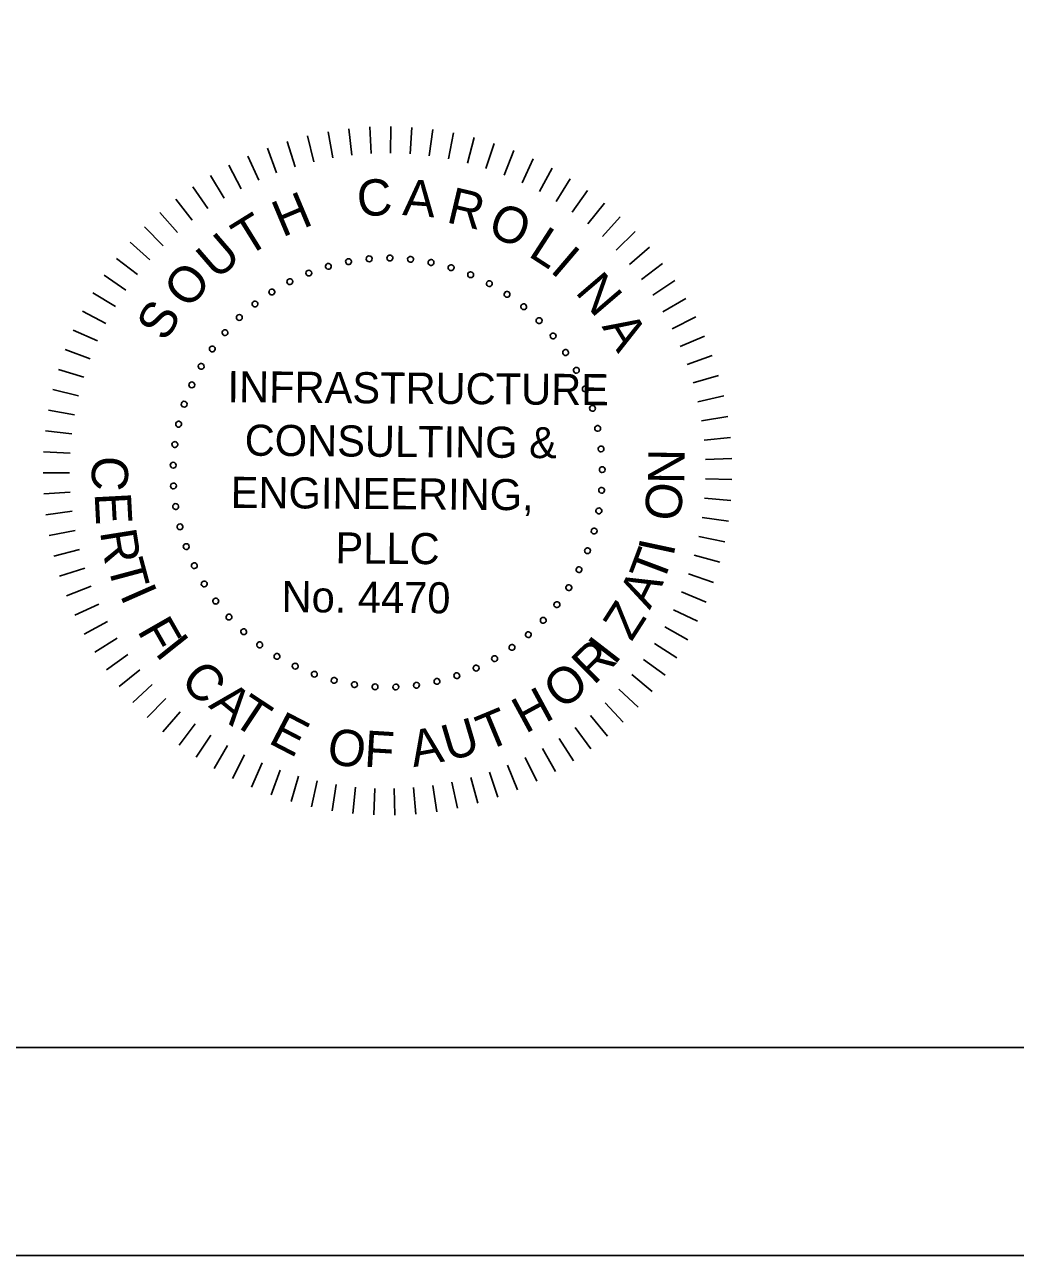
# Model space of a CAD drawing. Extents: x -125.5 to -89.3, y 42.4 to 64.4.
# Drawn here: x -100.072 to -97.692, y 42.449 to 45.407 of the extents above; entities that cross this region are included whole.
import ezdxf

# ---------------------------------------------------------------- set-up
doc = ezdxf.new("R2010")
doc.units = 0
for name, color, linetype in [('BR_BORDER LINES', 7, 'Continuous'), ('BR_TEXT', 7, 'Continuous'), ('Level 31', 7, 'Continuous')]:
    doc.layers.add(name, color=color, linetype=linetype)

msp = doc.modelspace()

# ---------------------------------------------------------------- linework, layer by layer
at = {"layer": 'BR_BORDER LINES'}
msp.add_line((-123.6994, 42.9486), (-90.0334, 42.9486), dxfattribs=at)
at = {"layer": 'BR_TEXT'}
for p, q in [((-99.343, 45.1496), (-99.332, 45.0869)), ((-99.2931, 45.1568), (-99.2858, 45.0935)), ((-99.2427, 45.1609), (-99.2394, 45.0974)), ((-99.1923, 45.162), (-99.1928, 45.0983)), ((-99.1418, 45.16), (-99.1462, 45.0965)), ((-99.0916, 45.1549), (-99.0999, 45.0918)), ((-99.0418, 45.1468), (-99.0539, 45.0842)), ((-99.4412, 45.1262), (-99.4226, 45.0653)), ((-99.3925, 45.1394), (-99.3776, 45.0775)), ((-98.9925, 45.1356), (-99.0084, 45.0739)), ((-98.9441, 45.1214), (-98.9637, 45.0609)), ((-99.5358, 45.0909), (-99.5099, 45.0328)), ((-99.489, 45.11), (-99.4667, 45.0504)), ((-98.8966, 45.1044), (-98.9199, 45.0451)), ((-99.5813, 45.0691), (-99.5519, 45.0126)), ((-98.8502, 45.0844), (-98.877, 45.0267)), ((-98.8051, 45.0617), (-98.8354, 45.0057)), ((-99.6253, 45.0445), (-99.5926, 44.9899)), ((-98.7615, 45.0363), (-98.7952, 44.9822)), ((-99.6678, 45.0172), (-99.6318, 44.9647)), ((-98.7195, 45.0082), (-98.7564, 44.9563)), ((-99.7086, 44.9874), (-99.6694, 44.9372)), ((-98.6793, 44.9777), (-98.7193, 44.9281)), ((-99.7475, 44.9552), (-99.7053, 44.9075)), ((-98.6411, 44.9447), (-98.684, 44.8977)), ((-99.7843, 44.9207), (-99.7393, 44.8756)), ((-98.6049, 44.9095), (-98.6506, 44.8652)), ((-99.819, 44.884), (-99.7713, 44.8418)), ((-98.571, 44.8722), (-98.6193, 44.8307)), ((-99.8513, 44.8452), (-99.8012, 44.806)), ((-98.5393, 44.8328), (-98.5901, 44.7944)), ((-99.8813, 44.8046), (-99.8288, 44.7685)), ((-98.5102, 44.7916), (-98.5632, 44.7564)), ((-99.9087, 44.7622), (-99.8541, 44.7293)), ((-98.4836, 44.7487), (-98.5387, 44.7167)), ((-99.9334, 44.7182), (-99.877, 44.6887)), ((-98.4597, 44.7042), (-98.5166, 44.6757)), ((-99.9555, 44.6728), (-99.8973, 44.6468)), ((-98.4385, 44.6584), (-98.497, 44.6334)), ((-99.9747, 44.6261), (-99.9151, 44.6037)), ((-98.4201, 44.6114), (-98.4801, 44.59)), ((-99.991, 44.5783), (-99.9302, 44.5596)), ((-98.4047, 44.5633), (-98.4659, 44.5456)), ((-100.0044, 44.5297), (-99.9426, 44.5147)), ((-98.3922, 44.5144), (-98.4544, 44.5005)), ((-100.0149, 44.4803), (-99.9522, 44.4691)), ((-98.3828, 44.4648), (-98.4456, 44.4547)), ((-100.0222, 44.4303), (-99.959, 44.423)), ((-98.3763, 44.4147), (-98.4397, 44.4085)), ((-100.0266, 44.38), (-99.963, 44.3766)), ((-98.373, 44.3644), (-98.4366, 44.362)), ((-100.0278, 44.3296), (-99.9641, 44.33)), ((-98.3727, 44.3139), (-98.4363, 44.3154)), ((-100.026, 44.2791), (-99.9625, 44.2834)), ((-98.3755, 44.2635), (-98.4389, 44.2688)), ((-100.0211, 44.2289), (-99.9579, 44.2371)), ((-98.3813, 44.2133), (-98.4443, 44.2226)), ((-100.0131, 44.179), (-99.9506, 44.191)), ((-98.3902, 44.1636), (-98.4525, 44.1767)), ((-100.0021, 44.1297), (-99.9405, 44.1455)), ((-98.4021, 44.1146), (-98.4635, 44.1314)), ((-99.9882, 44.0812), (-99.9276, 44.1008)), ((-98.417, 44.0663), (-98.4773, 44.0869)), ((-99.9713, 44.0336), (-99.912, 44.0569)), ((-98.4348, 44.0191), (-98.4937, 44.0433)), ((-99.9515, 43.9872), (-99.8937, 44.014)), ((-98.4554, 43.973), (-98.5128, 44.0007)), ((-99.9289, 43.942), (-99.8729, 43.9723)), ((-99.9037, 43.8983), (-99.8496, 43.9319)), ((-98.4789, 43.9283), (-98.5344, 43.9595)), ((-98.5049, 43.8851), (-98.5585, 43.9196)), ((-99.8758, 43.8563), (-99.8239, 43.8931)), ((-98.5336, 43.8435), (-98.5849, 43.8812)), ((-99.8454, 43.8159), (-99.7958, 43.8559)), ((-98.5648, 43.8038), (-98.6137, 43.8446)), ((-99.8126, 43.7776), (-99.7655, 43.8205)), ((-99.7775, 43.7413), (-99.7331, 43.7869)), ((-98.5983, 43.7661), (-98.6447, 43.8097)), ((-99.7403, 43.7072), (-99.6988, 43.7555)), ((-98.6341, 43.7304), (-98.6777, 43.7768)), ((-99.701, 43.6754), (-99.6626, 43.7261)), ((-98.6719, 43.697), (-98.7126, 43.746)), ((-99.6599, 43.6461), (-99.6246, 43.6991)), ((-98.7118, 43.666), (-98.7494, 43.7174)), ((-99.6171, 43.6193), (-99.5851, 43.6744)), ((-98.7967, 43.6116), (-98.8278, 43.6671)), ((-98.7534, 43.6375), (-98.7879, 43.6911)), ((-99.5728, 43.5953), (-99.5442, 43.6521)), ((-98.8416, 43.5883), (-98.8692, 43.6457)), ((-99.527, 43.5739), (-99.5019, 43.6324)), ((-99.48, 43.5554), (-99.4586, 43.6153)), ((-98.935, 43.5502), (-98.9555, 43.6105)), ((-98.8877, 43.5679), (-98.9118, 43.6268)), ((-99.432, 43.5398), (-99.4143, 43.6009)), ((-99.3832, 43.5271), (-99.3692, 43.5892)), ((-99.3336, 43.5175), (-99.3234, 43.5803)), ((-99.0821, 43.5151), (-99.0913, 43.5781)), ((-99.0324, 43.5238), (-99.0454, 43.5861)), ((-98.9833, 43.5355), (-99.0001, 43.597)), ((-99.2836, 43.5108), (-99.2772, 43.5742)), ((-99.2332, 43.5073), (-99.2307, 43.5709)), ((-99.1827, 43.5068), (-99.1841, 43.5705)), ((-99.1323, 43.5094), (-99.1376, 43.5729))]:
    msp.add_line(p, q, dxfattribs=at)
for centre, start, end in [((-99.2445, 44.844), 5.0653, 185.0653), ((-99.1947, 44.8459), 359.5268, 179.5268), ((-99.145, 44.8429), 353.9884, 173.9884), ((-99.3424, 44.8258), 16.1422, 196.1422), ((-99.3424, 44.8258), 196.1422, 16.1422), ((-99.2939, 44.8373), 10.6038, 190.6038), ((-99.2939, 44.8373), 190.6038, 10.6038), ((-99.2445, 44.844), 185.0653, 5.0653), ((-99.1947, 44.8459), 179.5268, 359.5268), ((-99.145, 44.8429), 173.9884, 353.9884), ((-99.0957, 44.8352), 168.4499, 348.4499), ((-99.0957, 44.8352), 348.4499, 168.4499), ((-99.0475, 44.8228), 162.9114, 342.9114), ((-99.0475, 44.8228), 342.9114, 162.9114), ((-99.435, 44.7892), 27.2191, 207.2191), ((-99.435, 44.7892), 207.2191, 27.2191), ((-99.3895, 44.8098), 21.6807, 201.6807), ((-99.3895, 44.8098), 201.6807, 21.6807), ((-99.0006, 44.8058), 157.373, 337.373), ((-99.0006, 44.8058), 337.373, 157.373), ((-98.9557, 44.7843), 331.8345, 151.8345), ((-99.4782, 44.7644), 32.7576, 212.7576), ((-99.4782, 44.7644), 212.7576, 32.7576), ((-98.9557, 44.7843), 151.8345, 331.8345), ((-98.913, 44.7586), 146.2961, 326.2961), ((-98.913, 44.7586), 326.2961, 146.2961), ((-99.5188, 44.7355), 38.2961, 218.2961), ((-99.5188, 44.7355), 218.2961, 38.2961), ((-98.873, 44.7289), 140.7576, 320.7576), ((-98.873, 44.7289), 320.7576, 140.7576), ((-99.5564, 44.7029), 43.8345, 223.8345), ((-99.5564, 44.7029), 223.8345, 43.8345), ((-98.836, 44.6955), 315.2191, 135.2191), ((-99.5907, 44.6667), 49.373, 229.373), ((-99.5907, 44.6667), 229.373, 49.373), ((-98.836, 44.6955), 135.2191, 315.2191), ((-98.8024, 44.6587), 129.6807, 309.6807), ((-98.8024, 44.6587), 309.6807, 129.6807), ((-99.6214, 44.6275), 54.9114, 234.9114), ((-99.6214, 44.6275), 234.9114, 54.9114), ((-98.7726, 44.6188), 124.1422, 304.1422), ((-98.7726, 44.6188), 304.1422, 124.1422), ((-99.6481, 44.5854), 60.4499, 240.4499), ((-99.6481, 44.5854), 240.4499, 60.4499), ((-98.7467, 44.5762), 118.6038, 298.6038), ((-98.7467, 44.5762), 298.6038, 118.6038), ((-99.6706, 44.541), 65.9884, 245.9884), ((-99.6706, 44.541), 245.9884, 65.9884), ((-98.7251, 44.5313), 113.0653, 293.0653), ((-98.7251, 44.5313), 293.0653, 113.0653), ((-99.6888, 44.4946), 71.5268, 251.5268), ((-99.6888, 44.4946), 251.5268, 71.5268), ((-98.7079, 44.4845), 107.5268, 287.5268), ((-98.7079, 44.4845), 287.5268, 107.5268), ((-99.7024, 44.4466), 77.0653, 257.0653), ((-99.7024, 44.4466), 257.0653, 77.0653), ((-98.6953, 44.4363), 101.9884, 281.9884), ((-98.6953, 44.4363), 281.9884, 101.9884), ((-99.7113, 44.3976), 82.6038, 262.6038), ((-99.7113, 44.3976), 262.6038, 82.6038), ((-98.6874, 44.3871), 96.4499, 276.4499), ((-98.6874, 44.3871), 276.4499, 96.4499), ((-99.7154, 44.3479), 88.1422, 268.1422), ((-99.7154, 44.3479), 268.1422, 88.1422), ((-98.6843, 44.3374), 90.9114, 270.9114), ((-98.6843, 44.3374), 270.9114, 90.9114), ((-99.7147, 44.2981), 93.6807, 273.6807), ((-99.7147, 44.2981), 273.6807, 93.6807), ((-98.686, 44.2876), 85.373, 265.373), ((-98.686, 44.2876), 265.373, 85.373), ((-99.7092, 44.2486), 99.2191, 279.2191), ((-99.7092, 44.2486), 279.2191, 99.2191), ((-98.6926, 44.2382), 79.8345, 259.8345), ((-98.6926, 44.2382), 259.8345, 79.8345), ((-99.6989, 44.1998), 104.7576, 284.7576), ((-99.6989, 44.1998), 284.7576, 104.7576), ((-98.7038, 44.1896), 74.2961, 254.2961), ((-98.7038, 44.1896), 254.2961, 74.2961), ((-99.684, 44.1523), 110.2961, 290.2961), ((-99.684, 44.1523), 290.2961, 110.2961), ((-98.7197, 44.1424), 68.7576, 248.7576), ((-98.7197, 44.1424), 248.7576, 68.7576), ((-99.6646, 44.1064), 115.8345, 295.8345), ((-99.6646, 44.1064), 295.8345, 115.8345), ((-98.7401, 44.0969), 63.2191, 243.2191), ((-98.7401, 44.0969), 243.2191, 63.2191), ((-99.6408, 44.0626), 121.373, 301.373), ((-99.6408, 44.0626), 301.373, 121.373), ((-98.7647, 44.0536), 57.6807, 237.6807), ((-98.7647, 44.0536), 237.6807, 57.6807), ((-99.6129, 44.0213), 126.9114, 306.9114), ((-99.6129, 44.0213), 306.9114, 126.9114), ((-98.7934, 44.0129), 52.1422, 232.1422), ((-98.7934, 44.0129), 232.1422, 52.1422), ((-99.5812, 43.9829), 132.4499, 312.4499), ((-99.5812, 43.9829), 312.4499, 132.4499), ((-98.826, 43.9751), 46.6038, 226.6038), ((-98.826, 43.9751), 226.6038, 46.6038), ((-99.5459, 43.9477), 137.9884, 317.9884), ((-99.5459, 43.9477), 317.9884, 137.9884), ((-98.862, 43.9407), 41.0653, 221.0653), ((-98.862, 43.9407), 221.0653, 41.0653), ((-99.5074, 43.9161), 143.5268, 323.5268), ((-99.5074, 43.9161), 323.5268, 143.5268), ((-98.9012, 43.9099), 35.5268, 215.5268), ((-98.9012, 43.9099), 215.5268, 35.5268), ((-99.466, 43.8884), 149.0653, 329.0653), ((-99.466, 43.8884), 329.0653, 149.0653), ((-98.9431, 43.883), 29.9884, 209.9884), ((-98.9431, 43.883), 209.9884, 29.9884), ((-99.4221, 43.8648), 154.6038, 334.6038), ((-99.4221, 43.8648), 334.6038, 154.6038), ((-99.3761, 43.8455), 160.1422, 340.1422), ((-99.3761, 43.8455), 340.1422, 160.1422), ((-99.0338, 43.842), 18.9114, 198.9114), ((-99.0338, 43.842), 198.9114, 18.9114), ((-98.9875, 43.8603), 24.4499, 204.4499), ((-98.9875, 43.8603), 204.4499, 24.4499), ((-99.3285, 43.8308), 165.6807, 345.6807), ((-99.3285, 43.8308), 345.6807, 165.6807), ((-99.2797, 43.8207), 171.2191, 351.2191), ((-99.2797, 43.8207), 351.2191, 171.2191), ((-99.2302, 43.8154), 356.7576, 176.7576), ((-99.2302, 43.8154), 176.7576, 356.7576), ((-99.1803, 43.8148), 2.2961, 182.2961), ((-99.1803, 43.8148), 182.2961, 2.2961), ((-99.1307, 43.8192), 7.8345, 187.8345), ((-99.1307, 43.8192), 187.8345, 7.8345), ((-99.0817, 43.8282), 13.373, 193.373), ((-99.0817, 43.8282), 193.373, 13.373)]:
    msp.add_arc(centre, 0.00701, start, end, dxfattribs=at)
at = {"layer": 'Level 31'}
msp.add_lwpolyline([(-125.5328, 42.4486), (-89.5328, 42.4486), (-89.5328, 64.4486), (-125.5328, 64.4486)], close=True, dxfattribs=at)

# ---------------------------------------------------------------- texts
at = {"layer": 'BR_TEXT'}
for s, height, rotation, p in [('C', 0.0872, 4.7281, (-99.2702, 44.9444)), ('A', 0.0872, 355.6981, (-99.1657, 44.9494)), ('H', 0.0872, 22.7882, (-99.453, 44.895)), ('R', 0.0872, 346.6681, (-99.0615, 44.9324)), ('O', 0.0872, 337.638, (-98.9637, 44.9026)), ('T', 0.0872, 31.8182, (-99.5379, 44.8474)), ('L', 0.0872, 327.108, (-98.8649, 44.8521)), ('U', 0.0872, 40.8482, (-99.6112, 44.7912)), ('I', 0.0872, 319.578, (-98.8123, 44.8143)), ('O', 0.0872, 49.8782, (-99.6782, 44.7202)), ('N', 0.0872, 310.548, (-98.7515, 44.7635)), ('S', 0.0872, 58.9083, (-99.7336, 44.6421)), ('A', 0.0872, 301.5179, (-98.6864, 44.6811)), ('INFRASTRUCTURE', 0.074771, 359.5268, (-99.585, 44.4995)), ('CONSULTING &', 0.074771, 359.5268, (-99.5437, 44.3709)), ('N', 0.0872, 89.2085, (-98.4872, 44.3024)), ('C', 0.0872, 267.025, (-99.9086, 44.3721)), ('ENGINEERING,', 0.074771, 359.5268, (-99.5773, 44.2455)), ('O', 0.0872, 83.2085, (-98.4982, 44.2109)), ('E', 0.0872, 273.025, (-99.9042, 44.2805)), ('R', 0.0872, 279.025, (-99.8914, 44.1883)), ('PLLC', 0.07477, 359.5268, (-99.3256, 44.1119)), ('T', 0.0872, 69.3954, (-98.5394, 44.0591)), ('I', 0.0872, 77.9093, (-98.5137, 44.1266)), ('T', 0.0872, 285.025, (-99.874, 44.1095)), ('I', 0.0872, 293.7713, (-99.8443, 44.0364)), ('No. 4470', 0.07477, 359.5268, (-99.4551, 43.995)), ('A', 0.0872, 63.3954, (-98.5702, 43.9988)), ('Z', 0.0872, 57.3954, (-98.6141, 43.9224)), ('F', 0.0872, 299.7713, (-99.8031, 43.9503)), ('I', 0.0872, 308.5268, (-99.761, 43.8965)), ('I', 0.0872, 52.3339, (-98.6551, 43.8648)), ('R', 0.0872, 44.5268, (-98.7045, 43.8175)), ('C', 0.0872, 314.5268, (-99.7017, 43.8264)), ('O', 0.0872, 38.5268, (-98.7811, 43.7575)), ('A', 0.0872, 320.5268, (-99.6325, 43.7678)), ('H', 0.0872, 28.5268, (-98.8692, 43.7015)), ('T', 0.0872, 326.5268, (-99.5781, 43.7293)), ('E', 0.0872, 332.5268, (-99.4895, 43.6815)), ('T', 0.0872, 22.5268, (-98.9624, 43.6597)), ('U', 0.0872, 16.5268, (-99.0541, 43.6354)), ('O', 0.0872, 350.5268, (-99.3494, 43.6326)), ('F', 0.0872, 356.5268, (-99.2579, 43.6235)), ('A', 0.0872, 10.5268, (-99.138, 43.6219))]:
    msp.add_text(s, height=height, rotation=rotation, dxfattribs=at).set_placement(p)

doc.saveas('drawing.dxf')
